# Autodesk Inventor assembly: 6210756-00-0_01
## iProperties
Category: PARTsolutions
Created: 2011-08
Part Number: 6210756-00-0_01
Catalog Web Link: www.cadenas.de
Description: S SX 1250 - Stahlketten
Document SubType Name: Assembly
Designer: PARTsolutions
NB: S 1250-242 (5125,380,7100,0,0622)
NN: S SX 1250
NT: Stahlketten
NBSYN: S 1250-242 (5125,380,7100,0,0622)
LINA: S 1250.242-380-5125 FAI/MAI
PSOL_MULTISOLIDPART: 0.0
TYP: S 1250
BI: 242
BK: 291
BST: 267
LK: 5125
KR: 380
LS: 7100
LV: 0
STEGV: 6
FA: 2
MA: 2
LF: 3737.500
ESP: 0
PSTOL: 0.010
T: 125.000
LS2: 3550.000
DR: 81.195
LB: 1568.805
EASS: 0.000
VAR: 1.000
LKA: 5250.000
MOD1: 0.000
RX2: 760.000
HI: 69
HG: 94
TYP1: S1250
BIMIN: 101.000
BIMAX: 751.000
KRV: 145,200,220,260,300,340,380,420,460,500,540,600,700
LSMAX: 150000.000
BKMIN: 150.000
BKMAX: 800.000
INFO: PDF Katalog
PPATH: assemblies/1250_asmtpl.prj
FABEST: FAI
MABEST: MAI
KT: DUMMY
CreationOption_UseAsmMates: 0
SUPPLIER: Kabelschlepp
ARTICLENO: S 1250-242 (5125,380,7100,0,0622)
BOMINFO: S 1250.242-380-5125 FAI/MAI
CREATOR: CADENAS GmbH
PSOL_IDENT_0: {\\10.0.0.251\ps_data\23d-libs\kabelschlepp\4_eketten_st\s_sx_1250_asmtab.prj},237 {VTYP=3D},{STYP=A
PSOL_IDENT_1: SSTAB},{NB=S 1250-242 (5125,380,7100,0,0622)},{LINA=S 1250.242-380-5125 FAI/MAI},{NN=S SX 1250},{DAT
PSOL_IDENT_2: E=14.01.2010 07:21:25},{GEOMDATE=17.03.2008},{VERSION=},{LINEID=10},{LINESUBID=-1},{WBVAR=BI,KR,LS,L
PSOL_IDENT_3: V,STEGV,FA,MA,ESP}  {NB=S 1250-242 (5125,380,7100,0,0622)},{LINA=S 1250.242-380-5125 FAI/MAI},{KT=DU
PSOL_IDENT_4: MMY},{TYP=S 1250},{BI=242},{BK=291},{BST=267},{LK=5125},{KR=380},{LS=7100},{LV=0},{STEGV=6},{FA=2},{
PSOL_IDENT_5: MA=2},{LF=3737.5},{ESP=0},{PSTOL=0.010},{T=125.000},{LS2=3550},{DR=81.194792},{LB=1568.805208},{EASS
PSOL_IDENT_6: =0},{VAR=1},{LKA=5250},{MOD1=0},{RX2=760},{NB1=},{HI=69},{HG=94},{TYP1=S1250},{BIMIN=101},{BIMAX=751
PSOL_IDENT_7: },{KRV=145,200,220,260,300,340,380,420,460,500,540,600,700},{LSMAX=150000.000},{SV=-1000000015047466
PSOL_IDENT_8: 200000000000000.00},{SV1=},{BKMIN=150},{BKMAX=800},{INFO=PDF Katalog},{PPATH=assemblies/1250_asmtpl.
PSOL_IDENT_9: prj},{FABEST=FAI},{MABEST=MAI}
Title: S 1250.242-380-5125 FAI/MAI
Author: Cadenas PARTsolutions
Comments: Stahlketten
